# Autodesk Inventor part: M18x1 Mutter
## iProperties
Shininess: 64.0
Length Units: 11269
Angle Units: 11279
Time Units: 11290
Mass Units: 11283
Length Display Precision: 3
Angle Display Precision: 2
Compacted: True
Part Number: M18x1 Mutter
Document SubType Name: Modeling
Created: 2003-04
Material: Standard
Designer: li
Density: 0.0
Volumn: 0.0
Area: 0.0
PropertySet Name: Model Information
Control State: 0
Master: False
Checked Out: False
Author: li
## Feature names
1. Extrusion1
2. Fase1 [Chamfer]
3. Fase2 [Chamfer]
4. Extrusion2
5. Fase3 [Chamfer]
6. Fase4 [Chamfer]
7. Extrusion3
